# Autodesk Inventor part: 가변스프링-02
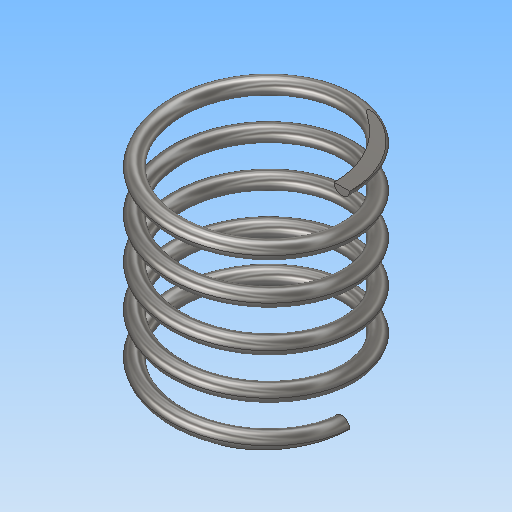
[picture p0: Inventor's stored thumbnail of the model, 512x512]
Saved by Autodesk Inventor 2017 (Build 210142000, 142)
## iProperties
Part Number: 가변스프링-02
Material: 강철, 연강
Document SubType Name: Modeling
Designer: MRC
Density: 7.85 g/cm^3
Appearance: 반연마
Mass: 8.38609 g
Surface Area: 21.6653 cm^2
Volume: 1.06829 cm^3
Author: MRC
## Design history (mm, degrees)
sketch "스케치1"
  geometry: L1 (0, 0)-(0, 26.358); L2 (0, 0)-(11, 0); L3 (0, 26.358)-(11, 26.358); C1 r 1 at (11, 0)
  constraints: 6 end point, 2 horizontal, 1 centre point, 1 coincident, 1 vertical
  dimensions: "d0" = 26.35829 distance of L1.start L1.end (derived); "d1" = 22 diameter of L2.end L1; "d2" = 2 diameter of C1; "d3" = 11 distance of L1.end L3.end
feature "코일1" sketch "스케치1" pitch "d4" = 10; turns "d6" = 5; dims "d5" = 26.35829 (= d0), "d7" = 0, angle "d8" = 90 deg, angle "d9" = 90 deg, "d10" = 0, "d11" = 0
sketch "스케치2"
  geometry: L1 (26.358, 12.5)-(0, 12.5); L2 (0, 12.5)-(0, -12.5); L3 (0, -12.5)-(26.358, -12.5); L4 (26.358, -12.5)-(26.358, 12.5); 2 further points
  constraints: 8 end point, 2 parallel, 1 coincident, 1 horizontal, 1 midpoint, 1 perpendicular
  dimensions: "d12" = 26.35829 distance of L2.end L3.end (= d0); "d13" = 25 distance of L3.end L1.start
extrude "돌출1" sketch "스케치2" stored distance "d14" = 0; taper "d15" = 0 deg
node "솔리드1"
